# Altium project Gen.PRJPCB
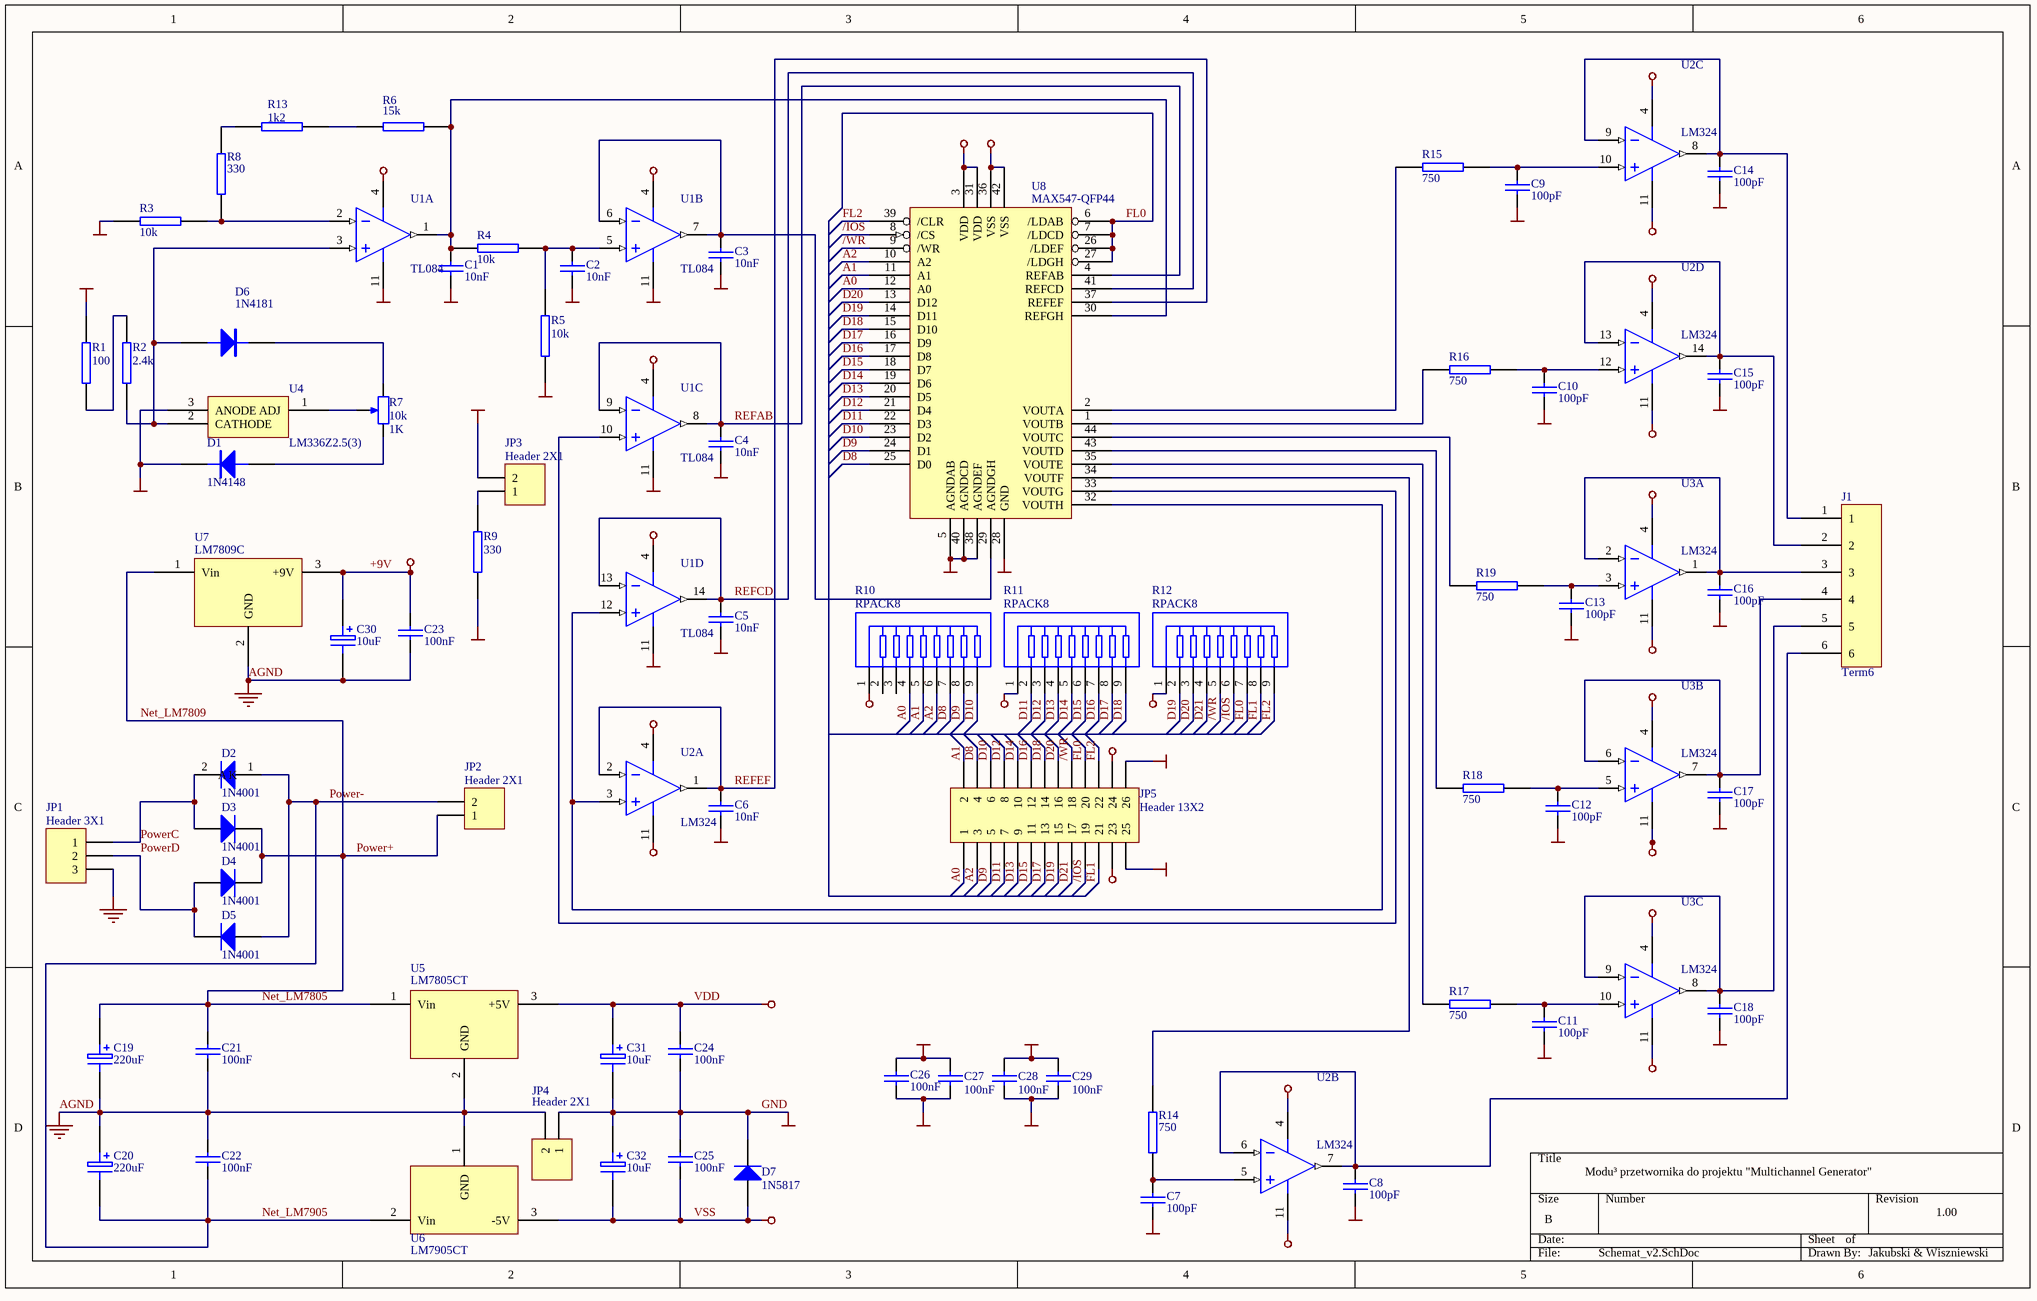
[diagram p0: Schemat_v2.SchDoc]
.TITLE: Modu³ procesorowy do projektu "Multichannel Generator"
3 sheets, 97 parts. Net scope: global (net labels, ports and power ports of the same name join across sheets).
Board files: PCB_V2_QFP2.PcbDoc, Proc_Modul.PCBDOC
Sheets:
  Schemat_v2.SchDoc
  Proc_Modul.SchDoc
  Kabel.SCHDOC

## Sheet Schemat_v2.SchDoc
size B

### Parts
(Parts that share a designator on the sheet are numbered #1, #2 ... from top to bottom, then left to right.)
C1#1  10nF  [RAD0.2]
C2#1  10nF  [RAD0.2]
C3#1  10nF  [RAD0.2]
C4#1  10nF  [RAD0.2]
C5#1  10nF  [RAD0.2]
C6#1  10nF  [RAD0.2]
C7#1  100pF  [RAD0.2]
C8#1  100pF  [RAD0.2]
C9#1  100pF  [RAD0.2]
C10#1  100pF  [RAD0.2]
C11#1  100pF  [RAD0.2]
C12#1  100pF  [RAD0.2]
C13#1  100pF  [RAD0.2]
C14#1  100pF  [RAD0.2]
C15#1  100pF  [RAD0.2]
C16  100pF  [RAD0.2]
C17  100pF  [RAD0.2]
C18  100pF  [RAD0.2]
C19  220uF  [RB.2/.4]
C20  220uF  [RB.2/.4]
C21  100nF  [RAD0.2]
C22  100nF  [RAD0.2]
C23  100nF  [RAD0.2]
C24  100nF  [RAD0.2]
C25  100nF  [RAD0.2]
C26  100nF  [RAD0.2]
C27  100nF  [RAD0.2]
C28  100nF  [RAD0.2]
C29  100nF  [RAD0.2]
C30  10uF  [RB.07/.2]
C31  10uF  [RB.07/.2]
C32  10uF  [RB.07/.2]
D1  1N4148  [DIODE0.4]
D2  1N4001  [DIODE0.4]
D3  1N4001  [DIODE0.4]
D4  1N4001  [DIODE0.4]
D5  1N4001  [DIODE0.4]
D6  1N4181  [DIODE0.4]
D7  1N5817  [Diode0.4]
J1#1  Term6  [TERM6-0.14_Bottom]
JP1#1  Header 3X1  [TERM3-0.2_Bottom]
JP2#1  Header 2X1  [HDR1X2_Bottom]
JP3  Header 2X1  [HDR1X2_Bottom]
JP4  Header 2X1  [HDR1X2_Bottom]
JP5  Header 13X2  [HDR2X13_Bottom]
R1#1  100  [AXIAL0.5]
R2  2.4k  [AXIAL0.5]
R3  10k  [AXIAL0.5]
R4  10k  [AXIAL0.5]
R5  10k  [AXIAL0.5]
R6  15k  [AXIAL0.5]
R7  10k  value 1K  [VR5_Bottom]
R8  330  [AXIAL0.5]
R9  330  [AXIAL0.5]
R10  RPACK8  [RPACK8]
R11  RPACK8  [RPACK8]
R12  RPACK8  [RPACK8]
R13  1k2  [AXIAL0.5]
R14  750  [AXIAL0.5]
R15  750  [AXIAL0.5]
R16  750  [AXIAL0.5]
R17  750  [AXIAL0.5]
R18  750  [AXIAL0.5]
R19  750  [AXIAL0.5]
U1#1  TL084  [DIP14]  (parts A,B,C,D of 4)
U2#1  LM324  [DIP14]  (parts A,B,C,D of 4)
U3#1  LM324  [DIP14]  (parts A,B,C of 4)
U4#1  LM336Z2.5(3)  [TO-92B]
U5  LM7805CT  [TO-220]
U6  LM7905CT  [TO-220]
U7  LM7809C  [TO-220]
U8  MAX547-QFP44  [QFP44-2]

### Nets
+9V: C23.2 C30.1 U2#1.4(VCC+) U3#1.4(VCC+) U7.3(+9V)
AGND: C7#1.2 C8#1.2 C9#1.2 C10#1.2 C11#1.2 C12#1.2 C13#1.2 C14#1.2 C15#1.2 C16.2 C17.2 C18.2 C19.2 C20.1 C21.1 C22.2 C23.1 C30.2 JP1#1.3 JP4.2 JP5.26 U5.2(GND) U6.1(GND) U7.2(GND) U8.5(AGNDAB) U8.38(AGNDEF) U8.40(AGNDCD)
GND: C1#1.2 C2#1.2 C3#1.2 C4#1.2 C5#1.2 C6#1.2 C24.1 C25.2 C26.2 C27.2 C28.2 C29.2 C31.2 C32.1 D1.2(K) D6.1(A) D7.2(K) JP4.1 JP5.25 R2.1 R3.2 R5.1 R9.1 U1#1.3(IN1+) U1#1.11(VCC-) U4#1.2(CATHODE) U4#1.3(ANODE) U8.28(GND)
VDD: C24.2 C28.1 C29.1 C31.1 JP5.23 R1#1.2 R10.1 R11.1 R12.1 U1#1.4(VCC+) U5.3(+5V) U8.3(VDD) U8.31(VDD)
VSS: C25.1 C26.1 C27.1 C32.2 D7.1(A) JP3.2 JP5.24 U2#1.11(VCC-) U3#1.11(VCC-) U6.3(-5V) U8.36(VSS) U8.42(VSS)
/IOS: JP5.19 R12.6 U8.8(/CS)
/WR: JP5.18 R12.5 U8.9(/WR)
A0: JP5.1 R10.4 U8.12(A0)
A1: JP5.2 R10.5 U8.11(A1)
A2: JP5.3 R10.6 U8.10(A2)
D8: JP5.4 R10.7 U8.25(D0)
D9: JP5.5 R10.8 U8.24(D1)
D10: JP5.6 R10.9 U8.23(D2)
D11: JP5.7 R11.2 U8.22(D3)
D12: JP5.8 R11.3 U8.21(D4)
D13: JP5.9 R11.4 U8.20(D5)
D14: JP5.10 R11.5 U8.19(D6)
D15: JP5.11 R11.6 U8.18(D7)
D16: JP5.12 R11.7 U8.17(D8)
D17: JP5.13 R11.8 U8.16(D9)
D18: JP5.14 R11.9 U8.15(D10)
D19: JP5.15 R12.2 U8.14(D11)
D20: JP5.16 R12.3 U8.13(D12)
D21: JP5.17 R12.4
FL0: JP5.20 R12.7 U8.6(/LDAB) U8.7(/LDCD) U8.26(/LDEF) U8.27(/LDGH)
FL1: JP5.21 R12.8
FL2: JP5.22 R12.9 U8.39(/CLR)
Net_LM7805: C19.1 C21.2 D3.2(K) D4.2(K) JP2#1.1 U5.1(Vin) U7.1(Vin)  [also labelled Net_LM7809, Power+]
Net_LM7905: C20.2 C22.1 D2.1(A) D5.1(A) JP2#1.2 U6.2(Vin)  [also labelled Power-]
PowerC: D2.2(K) D3.1(A) JP1#1.1
PowerD: D4.1(A) D5.2(K) JP1#1.2
REFAB: C4#1.1 U1#1.8(OUT) U1#1.9(IN3-) U8.4(REFAB)
REFCD: C5#1.1 U1#1.13(IN4-) U1#1.14(OUT) U8.41(REFCD)
REFEF: C6#1.1 U2#1.1(OUT) U2#1.2(IN1-) U8.37(REFEF)
NetC1#1_1: C1#1.1 R4.2 R6.1 U1#1.1(OUT) U8.30(REFGH)
NetC2#1_1: C2#1.1 R4.1 R5.2 U1#1.5(IN2+)
NetC3#1_1: C3#1.1 U1#1.6(IN2-) U1#1.7(OUT) U8.29(AGNDGH)
NetC7#1_1: C7#1.1 R14.2 U2#1.5(IN2+)
NetC8#1_1: C8#1.1 J1#1.6 U2#1.6(IN2-) U2#1.7(OUT)
NetC9#1_1: C9#1.1 R15.1 U2#1.10(IN3+)
NetC10#1_1: C10#1.1 R16.1 U2#1.12(IN4+)
NetC11#1_1: C11#1.1 R17.1 U3#1.10(IN3+)
NetC12#1_1: C12#1.1 R18.1 U3#1.5(IN2+)
NetC13#1_1: C13#1.1 R19.1 U3#1.3(IN1+)
NetC14#1_1: C14#1.1 J1#1.1 U2#1.8(OUT) U2#1.9(IN3-)
NetC15#1_1: C15#1.1 J1#1.2 U2#1.13(IN4-) U2#1.14(OUT)
NetC16_1: C16.1 J1#1.3 U3#1.1(OUT) U3#1.2(IN1-)
NetC17_1: C17.1 J1#1.4 U3#1.6(IN2-) U3#1.7(OUT)
NetC18_1: C18.1 J1#1.5 U3#1.8(OUT) U3#1.9(IN3-)
NetD1_1: D1.1(A) R7.3(BOT)
NetD6_2: D6.2(K) R7.1(TOP)
NetJP3_1: JP3.1 R9.2
NetR1#1_1: R1#1.1 R2.2
NetR3_1: R3.1 R8.1 U1#1.2(IN1-)
NetR6_2: R6.2 R13.2
NetR7_2: R7.2(TAP) U4#1.1(ADJ)
NetR8_2: R8.2 R13.1
NetR14_1: R14.1 U8.34(VOUTF)
NetR15_2: R15.2 U8.2(VOUTA)
NetR16_2: R16.2 U8.1(VOUTB)
NetR17_2: R17.2 U8.35(VOUTE)
NetR18_2: R18.2 U8.43(VOUTD)
NetR19_2: R19.2 U8.44(VOUTC)
NetU1#1_10: U1#1.10(IN3+) U8.33(VOUTG)
NetU1#1_12: U1#1.12(IN4+) U2#1.3(IN1+) U8.32(VOUTH)

Not connected (* = marked no-connect by the designer): R10 2 3

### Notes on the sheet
- Modu³ przetwornika do projektu "Multichannel Generator"
- 1.00
- Jakubski & Wiszniewski

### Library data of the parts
C1#1 C2#1 C3#1 C4#1 C5#1 C6#1 C7#1 C8#1 C9#1 C10#1 C11#1 C12#1 C13#1 C14#1 C15#1 C16-C18 C21-C29 = CAP: Capacitor
C19 C20 C30-C32 = ELECTRO1: Electrolytic Capacitor
D1 D6 = DIODE
D2-D5 D7 = Diode: Default Diode; Manufacturer: Generic Components; Class: Discrete; SubClass: Diode - Switching
JP1#1 = Header 3: Header, 3-Pin; Manufacturer: Generic Components; Class: Connector
JP2#1 JP3 JP4 = Header 2: Header, 2-Pin; Manufacturer: Generic Components; Class: Connector
JP5 = Header 13X2: Header, 13-Pin, Dual row; Manufacturer: Generic Components; Class: Connector
R1#1 R2-R6 R8 R9 R13-R19 = RES2
R7 = RPot2: Potentiometer; Manufacturer: Generic Components; Class: Passive; Set Position: 0.5
U1#1 U2#1 U3#1 = TL084: JFET-Input Operational Amplifiers
U4#1 = LM336Z2.5(3): ADJUSTABLE MICROPOWER VOLTAGE REFERENCES
U5 = MC7805T
U6 = MC7905T

## Sheet Proc_Modul.SchDoc
size B; DrawnBy: Jakubski & Wiszniewski; Revision: 1.00; SheetNumber: 1; SheetTotal: 1
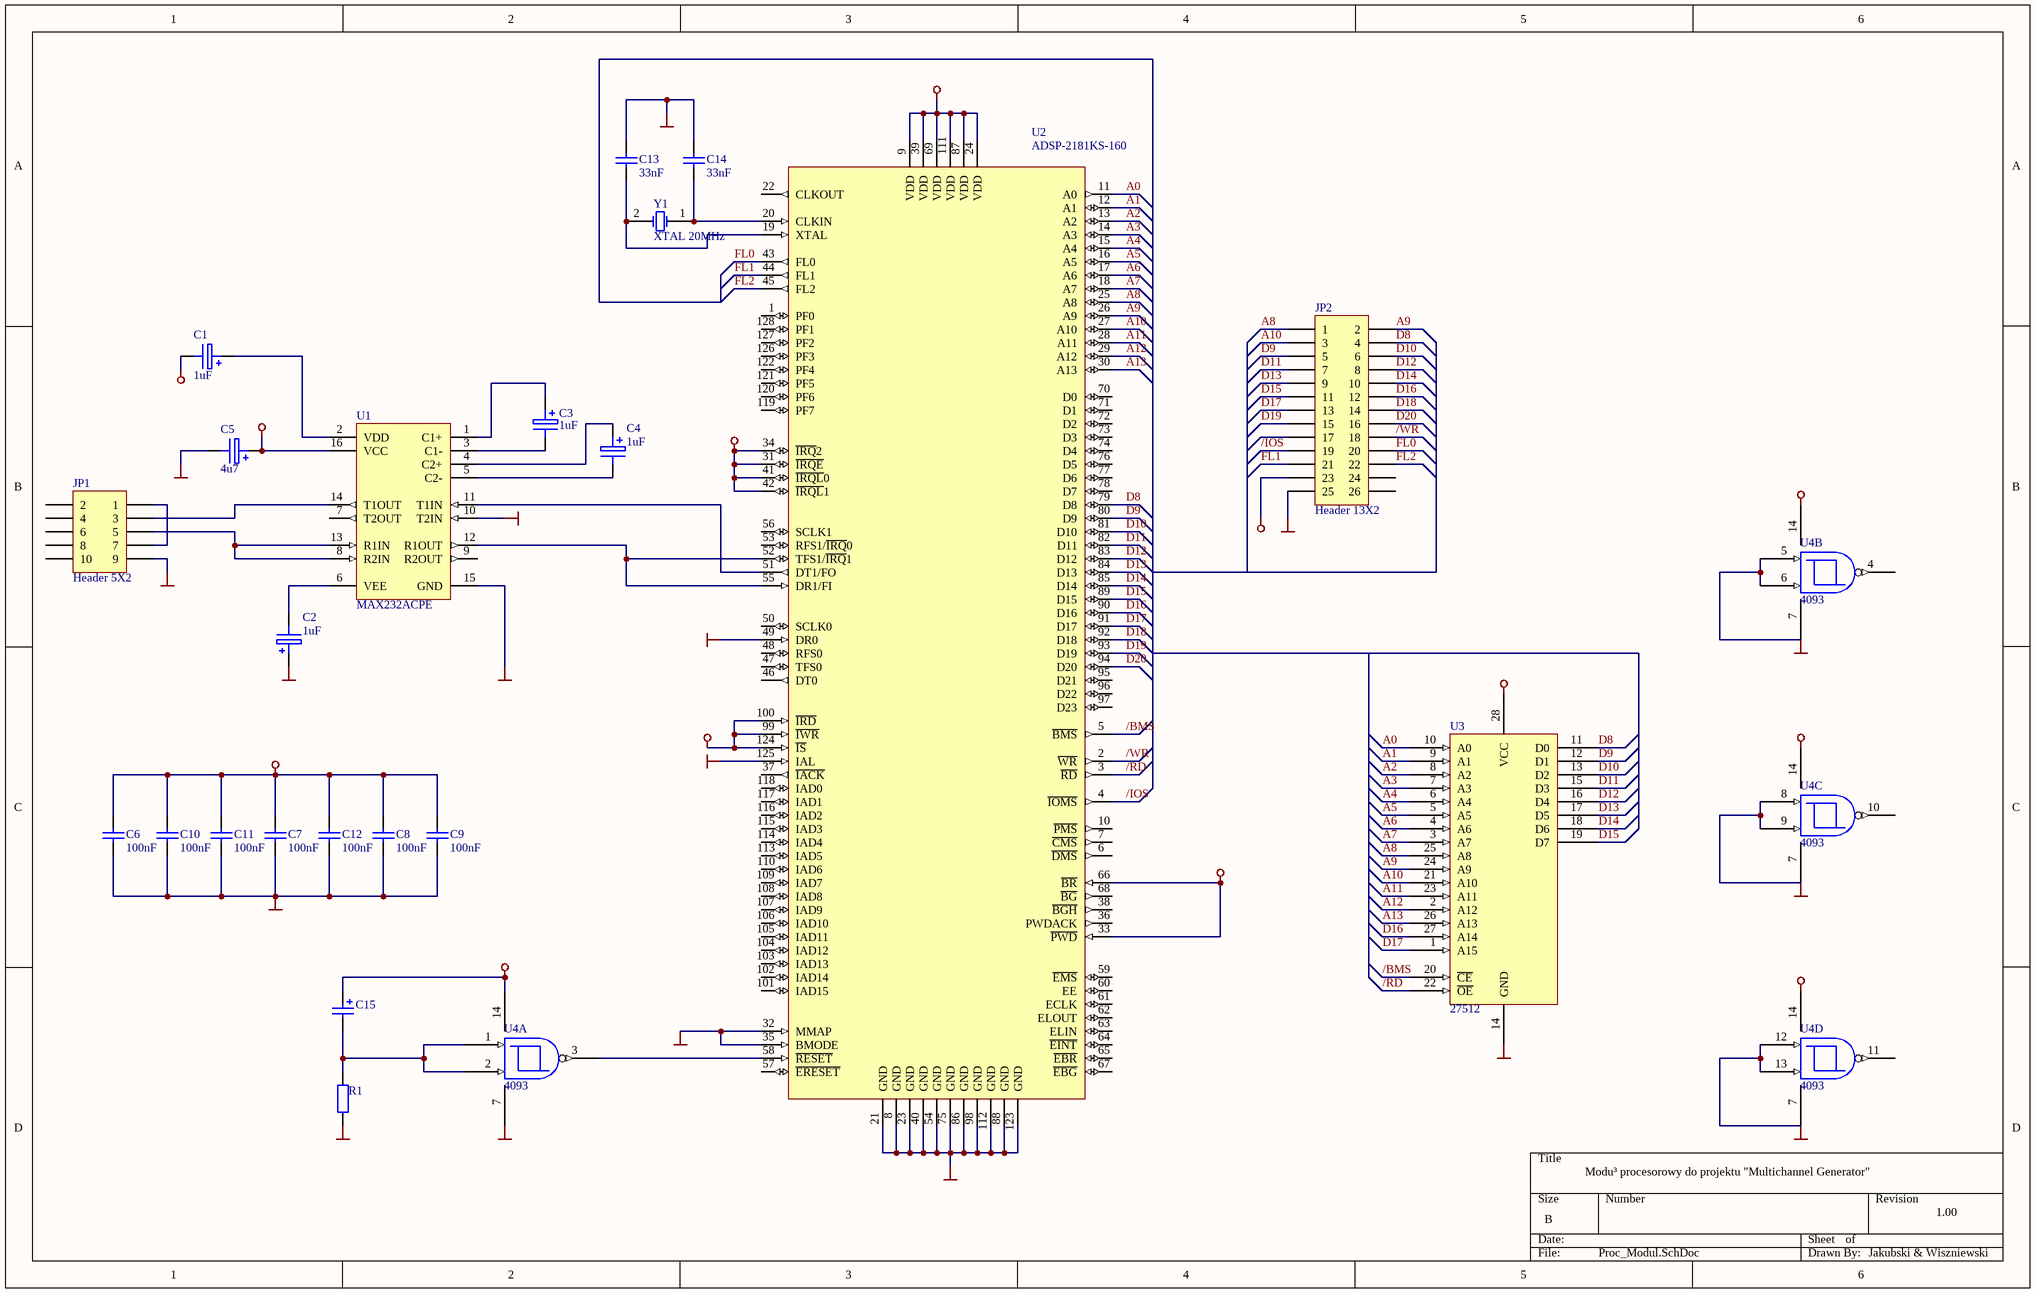
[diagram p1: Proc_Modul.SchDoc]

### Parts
(Parts that share a designator on the sheet are numbered #1, #2 ... from top to bottom, then left to right.)
C1#2  1uF  [RB-.2/.4]
C2#2  1uF  [RB-.2/.4]
C3#2  1uF  [RB-.2/.4]
C4#2  1uF  [RB-.2/.4]
C5#2  4u7  [RB-.2/.4]
C6#2  100nF  [RAD-0.2]
C7#2  100nF  [RAD-0.2]
C8#2  100nF  [RAD-0.2]
C9#2  100nF  [RAD-0.2]
C10#2  100nF  [RAD-0.2]
C11#2  100nF  [RAD-0.2]
C12#2  100nF  [RAD-0.2]
C13#2  33nF  [RAD-0.2]
C14#2  33nF  [RAD-0.2]
C15#2  10uF  [RB.07/.2]  (value not drawn)
JP1#2  Header 5X2  [HDR2X5]
JP2#2  Header 13X2  [HDR2X13]
R1#2  10k  [AXIAL-0.4]  (value not drawn)
U1#2  MAX232ACPE  [DIP-16/X1.5]
U2#2  ADSP-2181KS-160  [QFP28x28-G128/Y1.8N]
U3#2  27512  [DIP28]
U4#2  4093  [DIP-14]  (parts A,B,C,D of 4)
Y1  XTAL 20MHz  [BCY-W2/D3.1]

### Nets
GND: C2#2.1 C5#2.2 C6#2.1 C7#2.1 C8#2.1 C9#2.1 C10#2.1 C11#2.1 C12#2.1 C13#2.2 C14#2.2 JP1#2.9 JP2#2.25 R1#2.1 U1#2.10(T2IN) U1#2.15(GND) U2#2.8(GND) U2#2.21(GND) U2#2.23(GND) U2#2.32(MMAP) U2#2.35(BMODE) U2#2.40(GND) U2#2.49(DR0) U2#2.54(GND) U2#2.75(GND) U2#2.86(GND) U2#2.88(GND) U2#2.98(GND) U2#2.112(GND) U2#2.123(GND) U2#2.125(IAL) U3#2.14(GND) U4#2.5 U4#2.6 U4#2.7(GND) U4#2.8 U4#2.9 U4#2.12 U4#2.13
VDD: C1#2.2 C5#2.1 C6#2.2 C7#2.2 C8#2.2 C9#2.2 C10#2.2 C11#2.2 C12#2.2 C15#2.1 JP2#2.23 U1#2.16(VCC) U2#2.9(VDD) U2#2.24(VDD) U2#2.31(~{IRQE}) U2#2.33(~{PWD}) U2#2.34(~{IRQ}2) U2#2.39(VDD) U2#2.41(~{IRQL}0) U2#2.42(~{IRQL}1) U2#2.66(~{BR}) U2#2.69(VDD) U2#2.87(VDD) U2#2.99(~{IWR}) U2#2.100(~{IRD}) U2#2.111(VDD) U2#2.124(~{IS}) U3#2.28(VCC) U4#2.14(VCC)  [also labelled VCC]
/BMS: U2#2.5(~{BMS}) U3#2.20(~{CE})
/IOS: JP2#2.19 U2#2.4(~{IOMS})
/RD: U2#2.3(~{RD}) U3#2.22(~{OE})
/WR: JP2#2.18 U2#2.2(~{WR})
A0: U2#2.11(A0) U3#2.10(A0)
A1: U2#2.12(A1) U3#2.9(A1)
A2: U2#2.13(A2) U3#2.8(A2)
A3: U2#2.14(A3) U3#2.7(A3)
A4: U2#2.15(A4) U3#2.6(A4)
A5: U2#2.16(A5) U3#2.5(A5)
A6: U2#2.17(A6) U3#2.4(A6)
A7: U2#2.18(A7) U3#2.3(A7)
A8: JP2#2.1 U2#2.25(A8) U3#2.25(A8)
A9: JP2#2.2 U2#2.26(A9) U3#2.24(A9)
A10: JP2#2.3 U2#2.27(A10) U3#2.21(A10)
A11: U2#2.28(A11) U3#2.23(A11)
A12: U2#2.29(A12) U3#2.2(A12)
A13: U2#2.30(A13) U3#2.26(A13)
D8: JP2#2.4 U2#2.79(D8) U3#2.11(D0)
D9: JP2#2.5 U2#2.80(D9) U3#2.12(D1)
D10: JP2#2.6 U2#2.81(D10) U3#2.13(D2)
D11: JP2#2.7 U2#2.82(D11) U3#2.15(D3)
D12: JP2#2.8 U2#2.83(D12) U3#2.16(D4)
D13: JP2#2.9 U2#2.84(D13) U3#2.17(D5)
D14: JP2#2.10 U2#2.85(D14) U3#2.18(D6)
D15: JP2#2.11 U2#2.89(D15) U3#2.19(D7)
D16: JP2#2.12 U2#2.90(D16) U3#2.27(A14)
D17: JP2#2.13 U2#2.91(D17) U3#2.1(A15)
D18: JP2#2.14 U2#2.92(D18)
D19: JP2#2.15 U2#2.93(D19)
D20: JP2#2.16 U2#2.94(D20)
FL0: JP2#2.20 U2#2.43(FL0)
FL1: JP2#2.21 U2#2.44(FL1)
FL2: JP2#2.22 U2#2.45(FL2)
NetC1#2_1: C1#2.1 U1#2.2(VDD)
NetC2#2_2: C2#2.2 U1#2.6(VEE)
NetC3#2_1: C3#2.1 U1#2.1(C1+)
NetC3#2_2: C3#2.2 U1#2.3(C1-)
NetC4#2_1: C4#2.1 U1#2.4(C2+)
NetC4#2_2: C4#2.2 U1#2.5(C2-)
NetC13#2_1: C13#2.1 U2#2.19(XTAL) Y1.2(OSC2)
NetC14#2_1: C14#2.1 U2#2.20(CLKIN) Y1.1(OSC1)
NetC15#2_2: C15#2.2 R1#2.2 U4#2.1 U4#2.2
NetJP1#2_1: JP1#2.1 JP1#2.7
NetJP1#2_3: JP1#2.3 U1#2.14(T1OUT)
NetJP1#2_5: JP1#2.5 U1#2.8(R2IN) U1#2.13(R1IN)
NetU1#2_11: U1#2.11(T1IN) U2#2.51(DT1/FO)
NetU1#2_12: U1#2.12(R1OUT) U2#2.52(TFS1/~{IRQ}1) U2#2.55(DR1/FI)
NetU2#2_58: U2#2.58(~{RESET}) U4#2.3

Not connected (* = marked no-connect by the designer): JP1#2 2 4 6 8 10; JP2#2 17 24 26; U1#2 7(T2OUT) 9(R2OUT); U2#2 1(PF0) 6(~{DMS}) 7(~{CMS}) 10(~{PMS}) 22(CLKOUT) 36(PWDACK) 37(~{IACK}) 38(~{BGH}) 46(DT0) 47(TFS0) 48(RFS0) 50(SCLK0) 53(RFS1/~{IRQ}0) 56(SCLK1) 57(~{ERESET}) 59(~{EMS}) 60(EE) 61(ECLK) 62(ELOUT) 63(ELIN) 64(~{EINT}) 65(~{EBR}) 67(~{EBG}) 68(~{BG}) 70(D0) 71(D1) 72(D2) 73(D3) 74(D4) 76(D5) 77(D6) 78(D7) 95(D21) 96(D22) 97(D23) 101(IAD15) 102(IAD14) 103(IAD13) 104(IAD12) 105(IAD11) 106(IAD10) 107(IAD9) 108(IAD8) 109(IAD7) 110(IAD6) 113(IAD5) 114(IAD4) 115(IAD3) 116(IAD2) 117(IAD1) 118(IAD0) 119(PF7) 120(PF6) 121(PF5) 122(PF4) 126(PF3) 127(PF2) 128(PF1); U4#2 4 10 11

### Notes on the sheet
- Modu³ procesorowy do projektu "Multichannel Generator"
- 1.00
- Jakubski & Wiszniewski

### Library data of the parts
C1#2 C2#2 C3#2 C4#2 C5#2 = ELECTRO1
C6#2 C7#2 C8#2 C9#2 C10#2 C11#2 C12#2 = Cap: Capacitor; Manufacturer: Generic Components; Class: Passive
C13#2 C14#2 = Cap: Capacitor; Manufacturer: Generic Components; Class: Passive; Value: 100nF
C15#2 = Cap Pol1: Polarized Capacitor (Radial); Manufacturer: Generic Components; Class: Passive
JP1#2 = Header 5X2: Header, 5-Pin, Dual row; Manufacturer: Generic Components; Class: Connector
JP2#2 = Header 13X2: as JP5 on sheet Schemat_v2
R1#2 = Res2: Resistor; Manufacturer: Generic Components; Class: Passive
U1#2 = MAX232ACPE: +5V Powered, Multi-Channel RS-232 Driver/Receiver; Manufacturer: Maxim; Class I: Communication; Class II: Transceiver
U2#2 = ADSP-2181KS-160: 40 MIPS, 5V, 2 Serial Ports, Host Port, 80 KB RAM; Manufacturer: Analog Devices; Package Information: Latest Revision: 2000; Class I: Digital Signal Processor; Class II: 16-Bit
Y1 = XTAL: Crystal Oscillator; Manufacturer: Generic Components

## Sheet Kabel.SCHDOC
size B
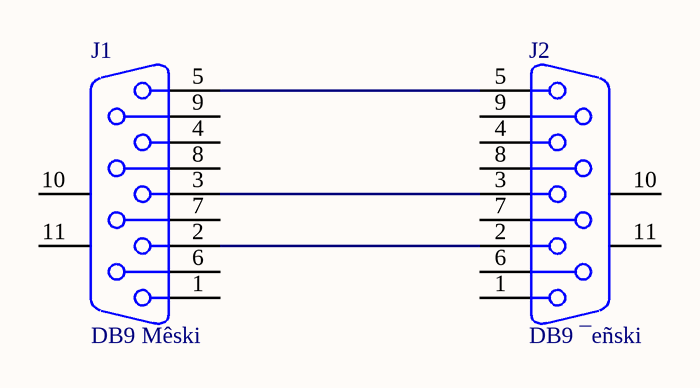
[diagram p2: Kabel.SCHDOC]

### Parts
(Parts that share a designator on the sheet are numbered #1, #2 ... from top to bottom, then left to right.)
J1#2  DB9 Mêski  [DSUB1.385-2H9]
J2  DB9 ¯eñski  [DSUB1.385-2H9]

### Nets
NetJ1#2_2: J1#2.2 J2.2
NetJ1#2_3: J1#2.3 J2.3
NetJ1#2_5: J1#2.5 J2.5

Not connected (* = marked no-connect by the designer): J1#2 1 4 6 7 8 9 10(MH1) 11(MH2); J2 1 4 6 7 8 9 10(MH1) 11(MH2)

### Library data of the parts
J1#2 J2 = D Connector 9: Receptacle Assembly, 9 Position, Right Angle; Manufacturer: Generic Components; Positions: 9

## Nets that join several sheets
GND: Schemat_v2 (28 pins), Proc_Modul (39 pins)
VDD: Schemat_v2 (13 pins), Proc_Modul (29 pins)
/IOS: Schemat_v2 (JP5.19 R12.6 U8.8), Proc_Modul (JP2#2.19 U2#2.4)
/WR: Schemat_v2 (JP5.18 R12.5 U8.9), Proc_Modul (JP2#2.18 U2#2.2)
A0: Schemat_v2 (JP5.1 R10.4 U8.12), Proc_Modul (U2#2.11 U3#2.10)
A1: Schemat_v2 (JP5.2 R10.5 U8.11), Proc_Modul (U2#2.12 U3#2.9)
A2: Schemat_v2 (JP5.3 R10.6 U8.10), Proc_Modul (U2#2.13 U3#2.8)
D8: Schemat_v2 (JP5.4 R10.7 U8.25), Proc_Modul (JP2#2.4 U2#2.79 U3#2.11)
D9: Schemat_v2 (JP5.5 R10.8 U8.24), Proc_Modul (JP2#2.5 U2#2.80 U3#2.12)
D10: Schemat_v2 (JP5.6 R10.9 U8.23), Proc_Modul (JP2#2.6 U2#2.81 U3#2.13)
D11: Schemat_v2 (JP5.7 R11.2 U8.22), Proc_Modul (JP2#2.7 U2#2.82 U3#2.15)
D12: Schemat_v2 (JP5.8 R11.3 U8.21), Proc_Modul (JP2#2.8 U2#2.83 U3#2.16)
D13: Schemat_v2 (JP5.9 R11.4 U8.20), Proc_Modul (JP2#2.9 U2#2.84 U3#2.17)
D14: Schemat_v2 (JP5.10 R11.5 U8.19), Proc_Modul (JP2#2.10 U2#2.85 U3#2.18)
D15: Schemat_v2 (JP5.11 R11.6 U8.18), Proc_Modul (JP2#2.11 U2#2.89 U3#2.19)
D16: Schemat_v2 (JP5.12 R11.7 U8.17), Proc_Modul (JP2#2.12 U2#2.90 U3#2.27)
D17: Schemat_v2 (JP5.13 R11.8 U8.16), Proc_Modul (JP2#2.13 U2#2.91 U3#2.1)
D18: Schemat_v2 (JP5.14 R11.9 U8.15), Proc_Modul (JP2#2.14 U2#2.92)
D19: Schemat_v2 (JP5.15 R12.2 U8.14), Proc_Modul (JP2#2.15 U2#2.93)
D20: Schemat_v2 (JP5.16 R12.3 U8.13), Proc_Modul (JP2#2.16 U2#2.94)
FL0: Schemat_v2 (6 pins), Proc_Modul (JP2#2.20 U2#2.43)
FL1: Schemat_v2 (JP5.21 R12.8), Proc_Modul (JP2#2.21 U2#2.44)
FL2: Schemat_v2 (JP5.22 R12.9 U8.39), Proc_Modul (JP2#2.22 U2#2.45)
